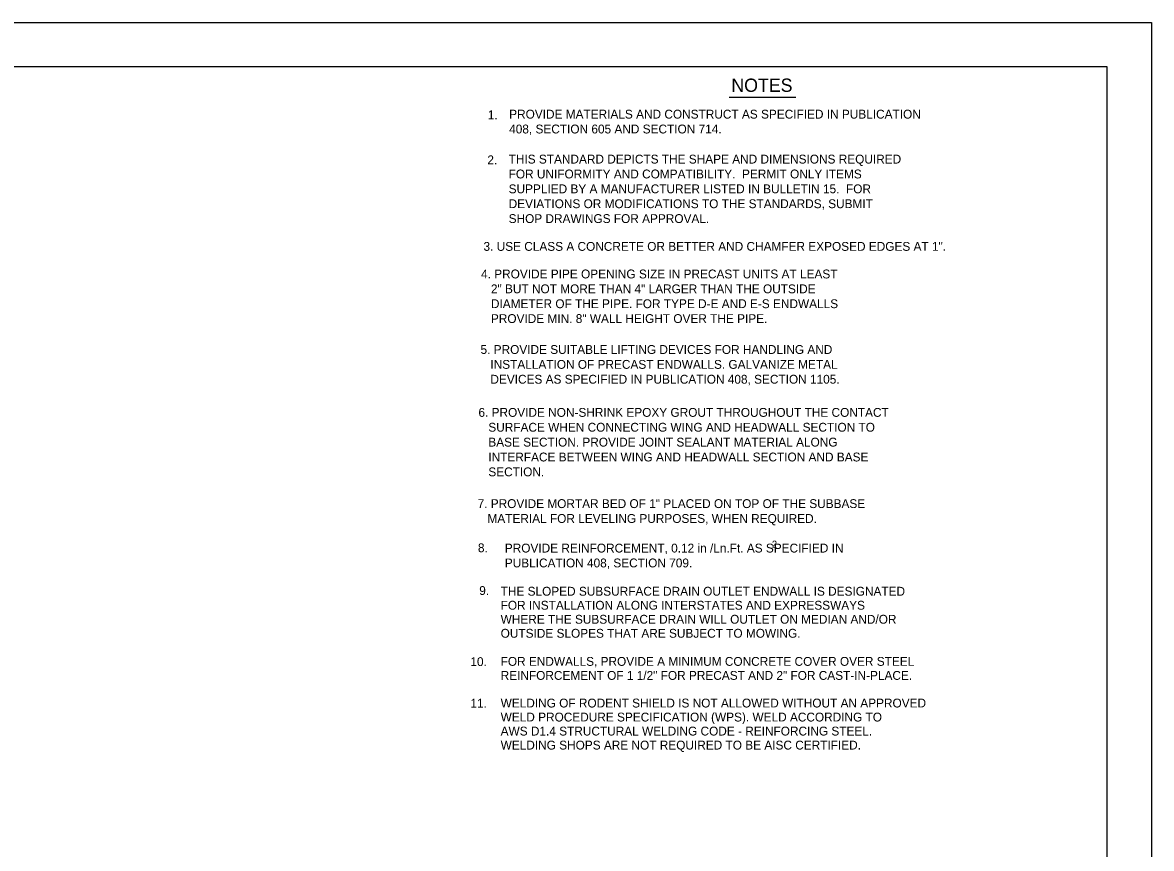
# Model space of a CAD drawing. Extents: x 638877 to 639960, y 297341 to 299123.
# Drawn here: x 639335.5 to 639718.2, y 298843.4 to 299123.3 of the extents above; entities that cross this region are included whole.
import ezdxf

# ---------------------------------------------------------------- set-up
doc = ezdxf.new("R2010")
doc.units = 0
for name, color, linetype in [('1', 7, 'Continuous'), ('3', 7, 'Continuous'), ('PLT-BNDY', 7, 'Continuous')]:
    doc.layers.add(name, color=color, linetype=linetype)

msp = doc.modelspace()

# ---------------------------------------------------------------- linework, layer by layer
at = {"layer": '1'}
msp.add_line((639575.02, 299097.96), (639597.69, 299097.96), dxfattribs=at)
msp.add_lwpolyline([(639703.19, 298544.28), (639703.19, 299108.28), (638917.19, 299108.28), (638917.19, 298544.28), (639703.19, 298544.28), (639703.19, 298570.64), (639503.19, 298570.64), (639503.19, 298635.32), (639703.19, 298635.32), (639703.19, 298664.28), (639503.19, 298664.28), (639503.19, 298544.28), (639581.99, 298544.28), (639581.99, 298570.64), (639581.99, 298544.28), (639658.99, 298544.28), (639658.99, 298570.64), (639658.99, 298558.33), (639703.19, 298558.33)], dxfattribs=at)
at = {"layer": 'PLT-BNDY'}
msp.add_lwpolyline([(638877.19, 299123.28), (639718.19, 299123.28), (639718.19, 298529.28), (638877.19, 298529.28)], close=True, dxfattribs=at)

# ---------------------------------------------------------------- texts
at = {"layer": '1'}
for s, height, p in [('PROVIDE MATERIALS AND CONSTRUCT AS SPECIFIED IN PUBLICATION', 3, (639500.47, 299090.75)), ('408, SECTION 605 AND SECTION 714.', 3, (639500.47, 299085.71)), ('THIS STANDARD DEPICTS THE SHAPE AND DIMENSIONS REQUIRED', 3, (639500.29, 299075.51)), ('FOR UNIFORMITY AND COMPATIBILITY.  PERMIT ONLY ITEMS', 3, (639500.29, 299070.47)), ('SUPPLIED BY A MANUFACTURER LISTED IN BULLETIN 15.  FOR', 3, (639500.29, 299065.43)), ('DEVIATIONS OR MODIFICATIONS TO THE STANDARDS, SUBMIT', 3, (639500.29, 299060.39)), ('SHOP DRAWINGS FOR APPROVAL.', 3, (639500.29, 299055.35)), ('4. PROVIDE PIPE OPENING SIZE IN PRECAST UNITS AT LEAST', 3, (639490.94, 299036.58)), ('   2" BUT NOT MORE THAN 4" LARGER THAN THE OUTSIDE', 3, (639490.94, 299031.54)), ('   DIAMETER OF THE PIPE. FOR TYPE D-E AND E-S ENDWALLS', 3, (639490.94, 299026.5)), ('   PROVIDE MIN. 8" WALL HEIGHT OVER THE PIPE.', 3, (639490.94, 299021.46)), ('5. PROVIDE SUITABLE LIFTING DEVICES FOR HANDLING AND', 3, (639490.76, 299010.98)), ('   INSTALLATION OF PRECAST ENDWALLS. GALVANIZE METAL', 3, (639490.76, 299005.94)), ('   DEVICES AS SPECIFIED IN PUBLICATION 408, SECTION 1105.', 3, (639490.76, 299000.9)), ('6. PROVIDE NON-SHRINK EPOXY GROUT THROUGHOUT THE CONTACT', 3, (639490.06, 298989.67)), ('   SURFACE WHEN CONNECTING WING AND HEADWALL SECTION TO', 3, (639490.06, 298984.63)), ('   BASE SECTION. PROVIDE JOINT SEALANT MATERIAL ALONG', 3, (639490.06, 298979.59)), ('   INTERFACE BETWEEN WING AND HEADWALL SECTION AND BASE', 3, (639490.06, 298974.55)), ('   SECTION.', 3, (639490.06, 298969.51)), ('7. PROVIDE MORTAR BED OF 1" PLACED ON TOP OF THE SUBBASE', 3, (639489.77, 298958.75)), ('   MATERIAL FOR LEVELING PURPOSES, WHEN REQUIRED.', 3, (639489.77, 298953.71)), ('8. ', 3, (639489.88, 298943.77)), ('PROVIDE REINFORCEMENT, 0.12 in /Ln.Ft. AS SPECIFIED IN', 3, (639498.99, 298943.68)), ('2', 2.4, (639589.51, 298945.28)), ('PUBLICATION 408, SECTION 709. ', 3, (639498.99, 298938.64)), ('9.', 3, (639490.32, 298929.29)), ('THE SLOPED SUBSURFACE DRAIN OUTLET ENDWALL IS DESIGNATED', 3, (639497.58, 298929.05)), ('FOR INSTALLATION ALONG INTERSTATES AND EXPRESSWAYS', 3, (639497.58, 298924.3)), ('WHERE THE SUBSURFACE DRAIN WILL OUTLET ON MEDIAN AND/OR', 3, (639497.58, 298919.55)), ('OUTSIDE SLOPES THAT ARE SUBJECT TO MOWING.', 3, (639497.58, 298914.8)), ('FOR ENDWALLS, PROVIDE A MINIMUM CONCRETE COVER OVER STEEL ', 3, (639497.58, 298905.28)), ('10.', 3, (639487.32, 298905.2)), ('REINFORCEMENT OF 1 1/2" FOR PRECAST AND 2" FOR CAST-IN-PLACE.', 3, (639497.58, 298900.53)), ('11.', 3, (639487.32, 298891.1)), ('WELDING OF RODENT SHIELD IS NOT ALLOWED WITHOUT AN APPROVED', 3, (639497.58, 298891.16)), ('WELD PROCEDURE SPECIFICATION (WPS). WELD ACCORDING TO ', 3, (639497.58, 298886.41)), ('AWS D1.4 STRUCTURAL WELDING CODE - REINFORCING STEEL. ', 3, (639497.58, 298881.66)), ('WELDING SHOPS ARE NOT REQUIRED TO BE AISC CERTIFIED.', 3, (639497.58, 298876.91))]:
    msp.add_text(s, height=height, dxfattribs=at).set_placement(p)
at = {"layer": '3'}
for s, height, p in [('NOTES', 4.5, (639575.79, 299099.81)), ('1.  ', 3, (639493.23, 299090.52)), ('2.  ', 3, (639493.08, 299075.26)), ('3. USE CLASS A CONCRETE OR BETTER AND CHAMFER EXPOSED EDGES AT 1".', 3, (639491.76, 299045.93))]:
    msp.add_text(s, height=height, dxfattribs=at).set_placement(p)

doc.saveas('drawing.dxf')
